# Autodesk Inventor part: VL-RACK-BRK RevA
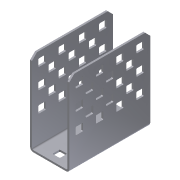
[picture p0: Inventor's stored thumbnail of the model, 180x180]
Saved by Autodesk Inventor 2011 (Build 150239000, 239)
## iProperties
Created: 2007-10
Part Number: VL-RACK-BRK RevA
Material: Steel
Document SubType Name: Modeling
Density: 7.85 g/cm^3
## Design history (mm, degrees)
feature "Base1"
workplane "Work Plane1"
sketch "Sketch1" dims "d5" = 25.4
  geometry: L1 (3.175, 50.419)-(47.625, 50.419) reference; L2 (3.175, 50.419)-(0, 47.244) reference; L3 (0, 0)-(0, 47.244) reference; L4 (50.8, 0)-(0, 0) reference; L5 (50.8, 47.244)-(50.8, 0) reference; L6 (50.8, 47.244)-(47.625, 50.419) reference; L7 (4.547, 16.434)-(8.153, 16.434) reference; L8 (4.039, 20.549)-(4.039, 16.942) reference; L9 (8.153, 21.057)-(4.547, 21.057) reference; L10 (8.661, 16.942)-(8.661, 20.549) reference; L11 (23.597, 22.784)-(27.203, 22.784) reference; L12 (23.089, 26.899)-(23.089, 23.292) reference; L13 (27.203, 27.407)-(23.597, 27.407) reference; L14 (27.711, 23.292)-(27.711, 26.899) reference; L15 (46.761, 45.949)-(46.761, 42.342) reference; L16 (46.253, 41.834)-(42.647, 41.834) reference; L17 (42.139, 42.342)-(42.139, 45.949) reference; L18 (42.647, 46.457)-(46.253, 46.457) reference; L19 (46.761, 33.249)-(46.761, 29.642) reference; L20 (46.253, 29.134)-(42.647, 29.134) reference; L21 (42.139, 29.642)-(42.139, 33.249) reference; L22 (42.647, 33.757)-(46.253, 33.757) reference; L23 (40.411, 39.599)-(40.411, 35.992) reference; L24 (39.903, 35.484)-(36.297, 35.484) reference; L25 (35.789, 35.992)-(35.789, 39.599) reference; L26 (36.297, 40.107)-(39.903, 40.107) reference; L27 (34.061, 45.949)-(34.061, 42.342) reference; L28 (33.553, 41.834)-(29.947, 41.834) reference; L29 (29.439, 42.342)-(29.439, 45.949) reference; L30 (29.947, 46.457)-(33.553, 46.457) reference; L31 (34.061, 33.249)-(34.061, 29.642) reference; L32 (33.553, 29.134)-(29.947, 29.134) reference; L33 (29.439, 29.642)-(29.439, 33.249) reference; L34 (29.947, 33.757)-(33.553, 33.757) reference; L35 (27.711, 39.599)-(27.711, 35.992) reference; L36 (27.203, 35.484)-(23.597, 35.484) reference; L37 (23.089, 35.992)-(23.089, 39.599) reference; L38 (23.597, 40.107)-(27.203, 40.107) reference; L39 (21.361, 45.949)-(21.361, 42.342) reference; L40 (20.853, 41.834)-(17.247, 41.834) reference; L41 (16.739, 42.342)-(16.739, 45.949) reference; L42 (17.247, 46.457)-(20.853, 46.457) reference; L43 (21.361, 33.249)-(21.361, 29.642) reference; L44 (20.853, 29.134)-(17.247, 29.134) reference; L45 (16.739, 29.642)-(16.739, 33.249) reference; L46 (17.247, 33.757)-(20.853, 33.757) reference; L47 (15.011, 39.599)-(15.011, 35.992) reference; L48 (14.503, 35.484)-(10.897, 35.484) reference; L49 (10.389, 35.992)-(10.389, 39.599) reference; L50 (10.897, 40.107)-(14.503, 40.107) reference; L51 (29.947, 16.434)-(33.553, 16.434) reference; L52 (29.439, 20.549)-(29.439, 16.942) reference; L53 (33.553, 21.057)-(29.947, 21.057) reference; L54 (34.061, 16.942)-(34.061, 20.549) reference; L55 (4.547, 33.757)-(8.153, 33.757) reference; L56 (8.661, 33.249)-(8.661, 29.642) reference; L57 (8.153, 29.134)-(4.547, 29.134) reference; L58 (4.039, 29.642)-(4.039, 33.249) reference; L59 (8.661, 45.949)-(8.661, 42.342) reference; L60 (8.153, 41.834)-(4.547, 41.834) reference; L61 (4.039, 42.342)-(4.039, 45.949) reference; L62 (4.547, 46.457)-(8.153, 46.457) reference; L63 (10.897, 22.784)-(14.503, 22.784) reference; L64 (10.389, 26.899)-(10.389, 23.292) reference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; C1 r 2.311 at (6.35, 31.445); C2 r 2.311 at (19.05, 31.445); C3 r 2.311 at (31.75, 31.445); C4 r 2.311 at (44.45, 31.445); A1 r 0.508 centre (8.153, 16.942) between (8.153, 16.434) and (8.661, 16.942) reference; A2 r 0.508 centre (4.547, 16.942) between (4.039, 16.942) and (4.547, 16.434) reference; A3 r 0.508 centre (4.547, 20.549) between (4.547, 21.057) and (4.039, 20.549) reference; A4 r 0.508 centre (8.153, 20.549) between (8.661, 20.549) and (8.153, 21.057) reference; A5 r 0.508 centre (27.203, 23.292) between (27.203, 22.784) and (27.711, 23.292) reference; A6 r 0.508 centre (23.597, 23.292) between (23.089, 23.292) and (23.597, 22.784) reference; A7 r 0.508 centre (23.597, 26.899) between (23.597, 27.407) and (23.089, 26.899) reference; A8 r 0.508 centre (27.203, 26.899) between (27.711, 26.899) and (27.203, 27.407) reference; A9 r 0.508 centre (46.253, 42.342) between (46.253, 41.834) and (46.761, 42.342) reference; A10 r 0.508 centre (42.647, 42.342) between (42.139, 42.342) and (42.647, 41.834) reference; A11 r 0.508 centre (42.647, 45.949) between (42.647, 46.457) and (42.139, 45.949) reference; A12 r 0.508 centre (46.253, 45.949) between (46.761, 45.949) and (46.253, 46.457) reference; A13 r 0.508 centre (46.253, 29.642) between (46.253, 29.134) and (46.761, 29.642) reference; A14 r 0.508 centre (42.647, 29.642) between (42.139, 29.642) and (42.647, 29.134) reference; A15 r 0.508 centre (42.647, 33.249) between (42.647, 33.757) and (42.139, 33.249) reference; A16 r 0.508 centre (46.253, 33.249) between (46.761, 33.249) and (46.253, 33.757) reference; A17 r 0.508 centre (39.903, 35.992) between (39.903, 35.484) and (40.411, 35.992) reference; A18 r 0.508 centre (36.297, 35.992) between (35.789, 35.992) and (36.297, 35.484) reference; A19 r 0.508 centre (36.297, 39.599) between (36.297, 40.107) and (35.789, 39.599) reference; A20 r 0.508 centre (39.903, 39.599) between (40.411, 39.599) and (39.903, 40.107) reference; A21 r 0.508 centre (33.553, 42.342) between (33.553, 41.834) and (34.061, 42.342) reference; A22 r 0.508 centre (29.947, 42.342) between (29.439, 42.342) and (29.947, 41.834) reference; A23 r 0.508 centre (29.947, 45.949) between (29.947, 46.457) and (29.439, 45.949) reference; A24 r 0.508 centre (33.553, 45.949) between (34.061, 45.949) and (33.553, 46.457) reference; A25 r 0.508 centre (33.553, 29.642) between (33.553, 29.134) and (34.061, 29.642) reference; A26 r 0.508 centre (29.947, 29.642) between (29.439, 29.642) and (29.947, 29.134) reference; A27 r 0.508 centre (29.947, 33.249) between (29.947, 33.757) and (29.439, 33.249) reference; A28 r 0.508 centre (33.553, 33.249) between (34.061, 33.249) and (33.553, 33.757) reference; A29 r 0.508 centre (27.203, 35.992) between (27.203, 35.484) and (27.711, 35.992) reference; A30 r 0.508 centre (23.597, 35.992) between (23.089, 35.992) and (23.597, 35.484) reference; A31 r 0.508 centre (23.597, 39.599) between (23.597, 40.107) and (23.089, 39.599) reference; A32 r 0.508 centre (27.203, 39.599) between (27.711, 39.599) and (27.203, 40.107) reference; A33 r 0.508 centre (20.853, 42.342) between (20.853, 41.834) and (21.361, 42.342) reference; A34 r 0.508 centre (17.247, 42.342) between (16.739, 42.342) and (17.247, 41.834) reference; A35 r 0.508 centre (17.247, 45.949) between (17.247, 46.457) and (16.739, 45.949) reference; A36 r 0.508 centre (20.853, 45.949) between (21.361, 45.949) and (20.853, 46.457) reference; A37 r 0.508 centre (20.853, 29.642) between (20.853, 29.134) and (21.361, 29.642) reference; A38 r 0.508 centre (17.247, 29.642) between (16.739, 29.642) and (17.247, 29.134) reference; A39 r 0.508 centre (17.247, 33.249) between (17.247, 33.757) and (16.739, 33.249) reference; A40 r 0.508 centre (20.853, 33.249) between (21.361, 33.249) and (20.853, 33.757) reference; A41 r 0.508 centre (14.503, 35.992) between (14.503, 35.484) and (15.011, 35.992) reference; A42 r 0.508 centre (10.897, 35.992) between (10.389, 35.992) and (10.897, 35.484) reference; A43 r 0.508 centre (10.897, 39.599) between (10.897, 40.107) and (10.389, 39.599) reference; A44 r 0.508 centre (14.503, 39.599) between (15.011, 39.599) and (14.503, 40.107) reference; A45 r 0.508 centre (33.553, 16.942) between (33.553, 16.434) and (34.061, 16.942) reference; A46 r 0.508 centre (29.947, 16.942) between (29.439, 16.942) and (29.947, 16.434) reference; A47 r 0.508 centre (29.947, 20.549) between (29.947, 21.057) and (29.439, 20.549) reference; A48 r 0.508 centre (33.553, 20.549) between (34.061, 20.549) and (33.553, 21.057) reference; A49 r 0.508 centre (8.153, 33.249) between (8.661, 33.249) and (8.153, 33.757) reference; A50 r 0.508 centre (8.153, 29.642) between (8.153, 29.134) and (8.661, 29.642) reference; A51 r 0.508 centre (4.547, 29.642) between (4.039, 29.642) and (4.547, 29.134) reference; A52 r 0.508 centre (4.547, 33.249) between (4.547, 33.757) and (4.039, 33.249) reference; A53 r 0.508 centre (8.153, 45.949) between (8.661, 45.949) and (8.153, 46.457) reference; A54 r 0.508 centre (8.153, 42.342) between (8.153, 41.834) and (8.661, 42.342) reference; A55 r 0.508 centre (4.547, 42.342) between (4.039, 42.342) and (4.547, 41.834) reference; A56 r 0.508 centre (4.547, 45.949) between (4.547, 46.457) and (4.039, 45.949) reference; A57 r 0.508 centre (14.503, 23.292) between (14.503, 22.784) and (15.011, 23.292) reference; A58 r 0.508 centre (10.897, 23.292) between (10.389, 23.292) and (10.897, 22.784) reference; A59 r 0.508 centre (10.897, 26.899) between (10.897, 27.407) and (10.389, 26.899) reference; A60 r 0.508 centre (14.503, 26.899) between (15.011, 26.899) and (14.503, 27.407) reference; A61 r 0.508 centre (39.903, 23.292) between (39.903, 22.784) and (40.411, 23.292) reference; A62 r 0.508 centre (36.297, 23.292) between (35.789, 23.292) and (36.297, 22.784) reference; A63 r 0.508 centre (36.297, 26.899) between (36.297, 27.407) and (35.789, 26.899) reference; A64 r 0.508 centre (39.903, 26.899) between (40.411, 26.899) and (39.903, 27.407) reference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
  constraints: 4 centre point, 4 tangent, 1 horizontal, 6 other
  dimensions: "d2" = 12.7 distance of C1.centre C2.centre
sketch "Sketch2" dims "d12" = 25.4
  geometry: L1 (0, 0)-(0, 47.244) reference; L2 (0, 47.244)-(-3.175, 50.419) reference; L3 (-3.175, 50.419)-(-47.625, 50.419) reference; L4 (-47.625, 50.419)-(-50.8, 47.244) reference; L5 (-50.8, 47.244)-(-50.8, 0) reference; L6 (0, 0)-(-50.8, 0) reference; L7 (-8.661, 16.942)-(-8.661, 20.549) reference; L8 (-8.153, 21.057)-(-4.547, 21.057) reference; L9 (-4.039, 20.549)-(-4.039, 16.942) reference; L10 (-4.547, 16.434)-(-8.153, 16.434) reference; L11 (-27.711, 23.292)-(-27.711, 26.899) reference; L12 (-27.203, 27.407)-(-23.597, 27.407) reference; L13 (-23.089, 26.899)-(-23.089, 23.292) reference; L14 (-23.597, 22.784)-(-27.203, 22.784) reference; L15 (-42.647, 46.457)-(-46.253, 46.457) reference; L16 (-42.139, 42.342)-(-42.139, 45.949) reference; L17 (-46.253, 41.834)-(-42.647, 41.834) reference; L18 (-46.761, 45.949)-(-46.761, 42.342) reference; L19 (-42.647, 33.757)-(-46.253, 33.757) reference; L20 (-42.139, 29.642)-(-42.139, 33.249) reference; L21 (-46.253, 29.134)-(-42.647, 29.134) reference; L22 (-46.761, 33.249)-(-46.761, 29.642) reference; L23 (-36.297, 40.107)-(-39.903, 40.107) reference; L24 (-35.789, 35.992)-(-35.789, 39.599) reference; L25 (-39.903, 35.484)-(-36.297, 35.484) reference; L26 (-40.411, 39.599)-(-40.411, 35.992) reference; L27 (-29.947, 46.457)-(-33.553, 46.457) reference; L28 (-29.439, 42.342)-(-29.439, 45.949) reference; L29 (-33.553, 41.834)-(-29.947, 41.834) reference; L30 (-34.061, 45.949)-(-34.061, 42.342) reference; L31 (-29.947, 33.757)-(-33.553, 33.757) reference; L32 (-29.439, 29.642)-(-29.439, 33.249) reference; L33 (-33.553, 29.134)-(-29.947, 29.134) reference; L34 (-34.061, 33.249)-(-34.061, 29.642) reference; L35 (-23.597, 40.107)-(-27.203, 40.107) reference; L36 (-23.089, 35.992)-(-23.089, 39.599) reference; L37 (-27.203, 35.484)-(-23.597, 35.484) reference; L38 (-27.711, 39.599)-(-27.711, 35.992) reference; L39 (-17.247, 46.457)-(-20.853, 46.457) reference; L40 (-16.739, 42.342)-(-16.739, 45.949) reference; L41 (-20.853, 41.834)-(-17.247, 41.834) reference; L42 (-21.361, 45.949)-(-21.361, 42.342) reference; L43 (-17.247, 33.757)-(-20.853, 33.757) reference; L44 (-16.739, 29.642)-(-16.739, 33.249) reference; L45 (-20.853, 29.134)-(-17.247, 29.134) reference; L46 (-21.361, 33.249)-(-21.361, 29.642) reference; L47 (-10.897, 40.107)-(-14.503, 40.107) reference; L48 (-10.389, 35.992)-(-10.389, 39.599) reference; L49 (-14.503, 35.484)-(-10.897, 35.484) reference; L50 (-15.011, 39.599)-(-15.011, 35.992) reference; L51 (-34.061, 16.942)-(-34.061, 20.549) reference; L52 (-33.553, 21.057)-(-29.947, 21.057) reference; L53 (-29.439, 20.549)-(-29.439, 16.942) reference; L54 (-29.947, 16.434)-(-33.553, 16.434) reference; L55 (-8.661, 33.249)-(-8.661, 29.642) reference; L56 (-4.547, 33.757)-(-8.153, 33.757) reference; L57 (-4.039, 29.642)-(-4.039, 33.249) reference; L58 (-8.153, 29.134)-(-4.547, 29.134) reference; L59 (-8.661, 45.949)-(-8.661, 42.342) reference; L60 (-4.547, 46.457)-(-8.153, 46.457) reference; L61 (-4.039, 42.342)-(-4.039, 45.949) reference; L62 (-8.153, 41.834)-(-4.547, 41.834) reference; L63 (-15.011, 23.292)-(-15.011, 26.899) reference; L64 (-14.503, 27.407)-(-10.897, 27.407) reference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; C1 r 2.311 at (-44.45, 31.445); C2 r 2.311 at (-31.75, 31.445); C3 r 2.311 at (-19.05, 31.445); C4 r 2.311 at (-6.35, 31.445); A1 r 0.508 centre (-8.153, 16.942) between (-8.661, 16.942) and (-8.153, 16.434) reference; A2 r 0.508 centre (-8.153, 20.549) between (-8.153, 21.057) and (-8.661, 20.549) reference; A3 r 0.508 centre (-4.547, 20.549) between (-4.039, 20.549) and (-4.547, 21.057) reference; A4 r 0.508 centre (-4.547, 16.942) between (-4.547, 16.434) and (-4.039, 16.942) reference; A5 r 0.508 centre (-27.203, 23.292) between (-27.711, 23.292) and (-27.203, 22.784) reference; A6 r 0.508 centre (-27.203, 26.899) between (-27.203, 27.407) and (-27.711, 26.899) reference; A7 r 0.508 centre (-23.597, 26.899) between (-23.089, 26.899) and (-23.597, 27.407) reference; A8 r 0.508 centre (-23.597, 23.292) between (-23.597, 22.784) and (-23.089, 23.292) reference; A9 r 0.508 centre (-46.253, 45.949) between (-46.253, 46.457) and (-46.761, 45.949) reference; A10 r 0.508 centre (-42.647, 45.949) between (-42.139, 45.949) and (-42.647, 46.457) reference; A11 r 0.508 centre (-42.647, 42.342) between (-42.647, 41.834) and (-42.139, 42.342) reference; A12 r 0.508 centre (-46.253, 42.342) between (-46.761, 42.342) and (-46.253, 41.834) reference; A13 r 0.508 centre (-46.253, 33.249) between (-46.253, 33.757) and (-46.761, 33.249) reference; A14 r 0.508 centre (-42.647, 33.249) between (-42.139, 33.249) and (-42.647, 33.757) reference; A15 r 0.508 centre (-42.647, 29.642) between (-42.647, 29.134) and (-42.139, 29.642) reference; A16 r 0.508 centre (-46.253, 29.642) between (-46.761, 29.642) and (-46.253, 29.134) reference; A17 r 0.508 centre (-39.903, 39.599) between (-39.903, 40.107) and (-40.411, 39.599) reference; A18 r 0.508 centre (-36.297, 39.599) between (-35.789, 39.599) and (-36.297, 40.107) reference; A19 r 0.508 centre (-36.297, 35.992) between (-36.297, 35.484) and (-35.789, 35.992) reference; A20 r 0.508 centre (-39.903, 35.992) between (-40.411, 35.992) and (-39.903, 35.484) reference; A21 r 0.508 centre (-33.553, 45.949) between (-33.553, 46.457) and (-34.061, 45.949) reference; A22 r 0.508 centre (-29.947, 45.949) between (-29.439, 45.949) and (-29.947, 46.457) reference; A23 r 0.508 centre (-29.947, 42.342) between (-29.947, 41.834) and (-29.439, 42.342) reference; A24 r 0.508 centre (-33.553, 42.342) between (-34.061, 42.342) and (-33.553, 41.834) reference; A25 r 0.508 centre (-33.553, 33.249) between (-33.553, 33.757) and (-34.061, 33.249) reference; A26 r 0.508 centre (-29.947, 33.249) between (-29.439, 33.249) and (-29.947, 33.757) reference; A27 r 0.508 centre (-29.947, 29.642) between (-29.947, 29.134) and (-29.439, 29.642) reference; A28 r 0.508 centre (-33.553, 29.642) between (-34.061, 29.642) and (-33.553, 29.134) reference; A29 r 0.508 centre (-27.203, 39.599) between (-27.203, 40.107) and (-27.711, 39.599) reference; A30 r 0.508 centre (-23.597, 39.599) between (-23.089, 39.599) and (-23.597, 40.107) reference; A31 r 0.508 centre (-23.597, 35.992) between (-23.597, 35.484) and (-23.089, 35.992) reference; A32 r 0.508 centre (-27.203, 35.992) between (-27.711, 35.992) and (-27.203, 35.484) reference; A33 r 0.508 centre (-20.853, 45.949) between (-20.853, 46.457) and (-21.361, 45.949) reference; A34 r 0.508 centre (-17.247, 45.949) between (-16.739, 45.949) and (-17.247, 46.457) reference; A35 r 0.508 centre (-17.247, 42.342) between (-17.247, 41.834) and (-16.739, 42.342) reference; A36 r 0.508 centre (-20.853, 42.342) between (-21.361, 42.342) and (-20.853, 41.834) reference; A37 r 0.508 centre (-20.853, 33.249) between (-20.853, 33.757) and (-21.361, 33.249) reference; A38 r 0.508 centre (-17.247, 33.249) between (-16.739, 33.249) and (-17.247, 33.757) reference; A39 r 0.508 centre (-17.247, 29.642) between (-17.247, 29.134) and (-16.739, 29.642) reference; A40 r 0.508 centre (-20.853, 29.642) between (-21.361, 29.642) and (-20.853, 29.134) reference; A41 r 0.508 centre (-14.503, 39.599) between (-14.503, 40.107) and (-15.011, 39.599) reference; A42 r 0.508 centre (-10.897, 39.599) between (-10.389, 39.599) and (-10.897, 40.107) reference; A43 r 0.508 centre (-10.897, 35.992) between (-10.897, 35.484) and (-10.389, 35.992) reference; A44 r 0.508 centre (-14.503, 35.992) between (-15.011, 35.992) and (-14.503, 35.484) reference; A45 r 0.508 centre (-33.553, 16.942) between (-34.061, 16.942) and (-33.553, 16.434) reference; A46 r 0.508 centre (-33.553, 20.549) between (-33.553, 21.057) and (-34.061, 20.549) reference; A47 r 0.508 centre (-29.947, 20.549) between (-29.439, 20.549) and (-29.947, 21.057) reference; A48 r 0.508 centre (-29.947, 16.942) between (-29.947, 16.434) and (-29.439, 16.942) reference; A49 r 0.508 centre (-8.153, 33.249) between (-8.153, 33.757) and (-8.661, 33.249) reference; A50 r 0.508 centre (-4.547, 33.249) between (-4.039, 33.249) and (-4.547, 33.757) reference; A51 r 0.508 centre (-4.547, 29.642) between (-4.547, 29.134) and (-4.039, 29.642) reference; A52 r 0.508 centre (-8.153, 29.642) between (-8.661, 29.642) and (-8.153, 29.134) reference; A53 r 0.508 centre (-8.153, 45.949) between (-8.153, 46.457) and (-8.661, 45.949) reference; A54 r 0.508 centre (-4.547, 45.949) between (-4.039, 45.949) and (-4.547, 46.457) reference; A55 r 0.508 centre (-4.547, 42.342) between (-4.547, 41.834) and (-4.039, 42.342) reference; A56 r 0.508 centre (-8.153, 42.342) between (-8.661, 42.342) and (-8.153, 41.834) reference; A57 r 0.508 centre (-14.503, 23.292) between (-15.011, 23.292) and (-14.503, 22.784) reference; A58 r 0.508 centre (-14.503, 26.899) between (-14.503, 27.407) and (-15.011, 26.899) reference; A59 r 0.508 centre (-10.897, 26.899) between (-10.389, 26.899) and (-10.897, 27.407) reference; A60 r 0.508 centre (-10.897, 23.292) between (-10.897, 22.784) and (-10.389, 23.292) reference; A61 r 0.508 centre (-39.903, 23.292) between (-40.411, 23.292) and (-39.903, 22.784) reference; A62 r 0.508 centre (-39.903, 26.899) between (-39.903, 27.407) and (-40.411, 26.899) reference; A63 r 0.508 centre (-36.297, 26.899) between (-35.789, 26.899) and (-36.297, 27.407) reference; A64 r 0.508 centre (-36.297, 23.292) between (-36.297, 22.784) and (-35.789, 23.292) reference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
  constraints: 4 centre point, 4 tangent, 1 horizontal, 6 other
  dimensions: "d9" = 12.7 distance of C1.centre C2.centre
body "Solid1"
